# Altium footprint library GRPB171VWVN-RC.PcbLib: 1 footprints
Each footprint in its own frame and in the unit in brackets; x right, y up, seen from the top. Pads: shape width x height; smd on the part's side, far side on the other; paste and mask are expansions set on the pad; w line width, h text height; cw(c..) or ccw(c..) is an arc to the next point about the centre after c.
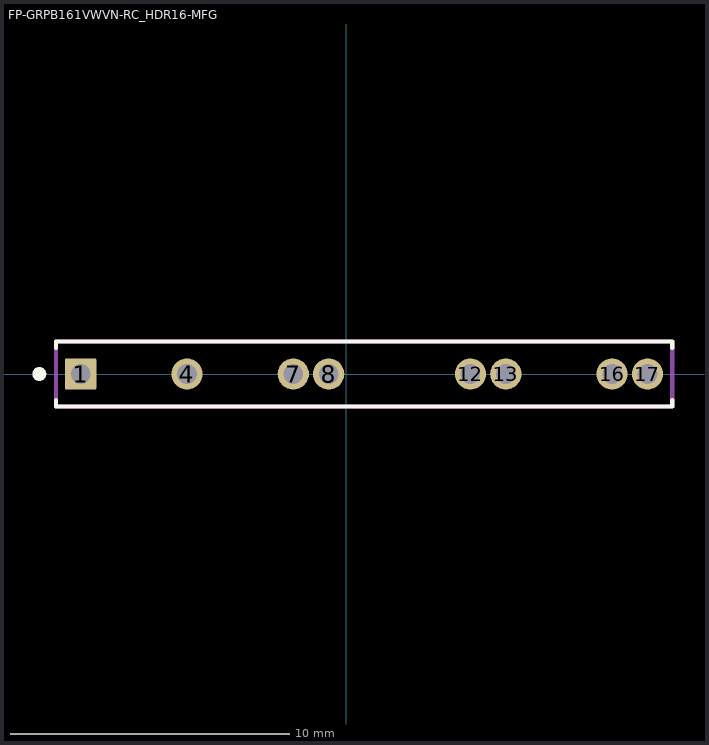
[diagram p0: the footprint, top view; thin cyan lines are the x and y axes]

## FP-GRPB161VWVN-RC_HDR16-MFG [mm]
pads (8):
  rrect9% 1.12x1.12 hole 0.7 paste-1000 mask+0: 1(-9.525,0)
  round 1.12 hole 0.7 paste-1000 mask+0: 4(-5.715,0) 7(-1.905,0) 8(-0.635,0) 12(4.445,0) 13(5.715,0) 16(9.525,0) 17(10.795,0)
Top Overlay:
  circle w0.25: c-11.01,0 r0.125
  lines w0.15: -10.41,-0.935 -10.41,-1.17 11.68,-1.17 11.68,-0.935 ; -10.41,0.935 -10.41,1.17 11.68,1.17 11.68,0.935
Mechanical 5:
  lines w0.15: -10.41,-1.17 11.68,-1.17 11.68,1.17 -10.41,1.17 -10.41,-1.17
  text ".Designator" at 0,0 h0.5
3D body "Conn_GRPB161VWVN-RC_HDR16.STEP": height 0.25, standoff 0, extent -10.51,-1.27 10.51,1.27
